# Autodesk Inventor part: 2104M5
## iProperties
Shininess: 40.0
Length Units: 11269
Angle Units: 11279
Time Units: 11290
Mass Units: 11284
Length Display Precision: 3
Angle Display Precision: 2
Compacted: True
Company: Pneumax S.p.A.
Part Number: 2104M5
Material: Default
Description: T LATERALE GIREVOLE Ø4 M5
Document SubType Name: Modellazione
Catalog Web Link: www.pneumaxspa.com
Density: 1.59
Volumn: 0.8648857994912436
Area: 17.092995283760587
PropertySet Name: Model Information
Control State: 0
Master: False
Checked Out: False
Revision Number: 0
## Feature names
1. Revolution6
2. Hole9
3. Revolution12
4. Circular Pattern10
5. Circular Pattern11
6. Circular Pattern12
7. Revolution7
8. Revolution11
9. Revolution9
10. Extrusion11
11. Circular Pattern8
12. Hole7
13. Chamfer10
14. REV_M5 [Revolution]
15. FORO_M5 [Hole]
16. ESTRU_M5 [Extrusion]
17. ARRY_M5 [Circular Pattern]
18. FORO_M52 [Hole]
19. SMM5 [Chamfer]
